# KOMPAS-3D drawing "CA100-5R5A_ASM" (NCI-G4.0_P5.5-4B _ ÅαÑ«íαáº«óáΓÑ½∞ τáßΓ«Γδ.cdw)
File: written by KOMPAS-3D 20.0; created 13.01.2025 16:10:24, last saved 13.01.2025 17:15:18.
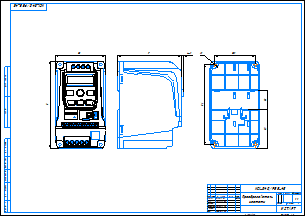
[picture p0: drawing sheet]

Sheet 1: A2, landscape

Document properties: Автор: admin; Полное имя файла: P:\INSTART\Технический отдел\ОР\Прочие задачи\КД на номенклатурный ряд\КД на типоразмеры ПЧ\NCI\NCI-G4.0_P5.5-4B\NCI-G4.0_P5.5-4B _ Преобразователь частоты.cdw

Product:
- Part/product: CA100-5R5A_ASM
    Масса: 7.13181
    Комментарий: NOT SPECIFIED
  - Component [detail]: AA  | Масса: 1.44663; source file: C:\Уралов Работа\Уралов (локальная)\ПЧ\! Китай 3Д-модель NCI\NCI 4.0-7.5 4B\AA.m3d
  - Component [detail]: CA100-2R2A-SJ-04  | Масса: 0.00516082; source file: C:\Уралов Работа\Уралов (локальная)\ПЧ\! Китай 3Д-модель NCI\NCI 4.0-7.5 4B\CA100-2R2A-SJ-04.m3d
  - Component [assembly]: JIANPAN99_ASM_ASM  | Масса: 0.107178; Комментарий: NOT SPECIFIED; source file: C:\Уралов Работа\Уралов (локальная)\ПЧ\! Китай 3Д-модель NCI\NCI 4.0-7.5 4B\JIANPAN99_ASM_ASM.a3d
  - Component [assembly]: CA100-5R5A-SJ_ASM  | Масса: 1.6976; Комментарий: NOT SPECIFIED; source file: C:\Уралов Работа\Уралов (локальная)\ПЧ\! Китай 3Д-модель NCI\NCI 4.0-7.5 4B\CA100-5R5A-SJ_ASM.a3d
  - Component [assembly]: PCB_ASM  | Масса: 1.9346; source file: C:\Уралов Работа\Уралов (локальная)\ПЧ\! Китай 3Д-модель NCI\NCI 4.0-7.5 4B\PCB_ASM.a3d
  - Component [assembly]: QJ_ASM  | Масса: 0.208727; source file: C:\Уралов Работа\Уралов (локальная)\ПЧ\! Китай 3Д-модель NCI\NCI 4.0-7.5 4B\QJ_ASM.a3d
  - Component [detail]: CA100-4R0A-SR-01  | Масса: 0.923365; source file: C:\Уралов Работа\Уралов (локальная)\ПЧ\! Китай 3Д-модель NCI\NCI 4.0-7.5 4B\CA100-4R0A-SR-01.m3d
  - Component [detail]: CA100-5R5A-SR-01  | Масса: 0.808548; source file: C:\Уралов Работа\Уралов (локальная)\ПЧ\! Китай 3Д-модель NCI\NCI 4.0-7.5 4B\CA100-5R5A-SR-01.m3d

Title block, sheet 1: Наименование: Преобразователь / частоты; designation: NCI-G4.0/P5.5-4B; Количество листов документа: 1; organisation: INSTART; cell 10: Согласовано; Форматы листов документа: A2; Разработал: Уралов Д.А.; Проверил: Андреев Н.В.; Подписал: Смелков Ж.Е.; Утвердил: Ефремов И.Н.; Разработал, date: 13.01.25

Views: Вид 1, Проекционный вид 2
Referenced files in C:\Уралов Работа\Уралов (локальная)\ПЧ\! Китай 3Д-модель NCI\NCI 4.0-7.5 4B\: CA100-4R0A-SR-01.m3d, CA100-5R5A-SR-01.m3d, 6025.m3d, QJ_ASM.a3d, QDB.m3d, DRI.m3d, 6912184100XX_MASS.m3d, 6912184100XX_PIN.m3d, 6912184100XX_VIS.m3d, 691218410003.m3d, ASSEM1_ASM.a3d, EU5-03-952_ASM.a3d, QDB_ASM.a3d, 2R2-CM.m3d, EU1_5-14-5_08-00_1_.m3d, LED.m3d, DWQ_2.m3d, ANJIAN.m3d, BM.m3d, 485.m3d, 2R2-CM_ASM.a3d, DRB.m3d, DR.m3d, DRB_ASM.a3d, PCB_ASM.a3d, CA100-5R5A-SJ-01.m3d, CA100-5R5A-SJ-02.m3d, CA100-5R5A-SJ-01-.m3d, CA100-5R5A-SJ_ASM.a3d, CA100-2R2A-SJ-05_45.m3d, CA100-2R2A-SJ-06_23.m3d, CA100-2R2A-SJ-03_22.m3d, JIANPAN99_ASM_17_ASM.a3d, JIANPAN99_ASM_ASM.a3d, CA100-2R2A-SJ-04.m3d, AA.m3d, NCI 4.0-7.5 4B.a3d
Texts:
  CA100-4R0A-SR-01
  CA100-4R0A-SR-01 CA100-4R0A-SR-01
  CA100-5R5A-SR-01
  CA100-5R5A-SR-01 CA100-5R5A-SR-01
  QJ_ASM QJ_ASM
  QDB
  QDB QDB
  DRI
  DRI DRI
  6912184100XX_MASS 6912184100XX_MASS
  6912184100XX_PIN 6912184100XX_PIN
  6912184100XX_VIS 6912184100XX_VIS
  ASSEM1_ASM ASSEM1_ASM
  EU5-03-952_ASM
  EU5-03-952_ASM EU5-03-952_ASM
  QDB_ASM QDB_ASM
  EU1_5-14-5_08-00_1_
  EU1_5-14-5_08-00_1_ EU1_5-14-5_08-00_1_
  LED
  LED LED
  DWQ_2 DWQ_2
  ANJIAN
  ANJIAN ANJIAN
  BM BM
  DRB
  DRB DRB
  DR DR
  DRB_ASM DRB_ASM
  PCB_ASM PCB_ASM
  CA100-5R5A-SJ-01
  CA100-5R5A-SJ-01 CA100-5R5A-SJ-01
  CA100-5R5A-SJ-02
  CA100-5R5A-SJ-02 CA100-5R5A-SJ-02
  CA100-5R5A-SJ-01-
  CA100-5R5A-SJ-01- CA100-5R5A-SJ-01-
  CA100-5R5A-SJ_ASM
  CA100-5R5A-SJ_ASM CA100-5R5A-SJ_ASM
  CA100-2R2A-SJ-05_45
  CA100-2R2A-SJ-05_45 CA100-2R2A-SJ-05_45
  CA100-2R2A-SJ-06_23
  CA100-2R2A-SJ-06_23 CA100-2R2A-SJ-06_23
  CA100-2R2A-SJ-03_22
  CA100-2R2A-SJ-03_22 CA100-2R2A-SJ-03_22
  JIANPAN99_ASM_17_ASM JIANPAN99_ASM_17_ASM
  JIANPAN99_ASM_ASM JIANPAN99_ASM_ASM
  Поверхности
  CA100-2R2A-SJ-04
  CA100-2R2A-SJ-04 CA100-2R2A-SJ-04
  AA AA
  CA100-5R5A_ASM
  CA100-5R5A_ASM CA100-5R5A_ASM
Dimensions and other numbers on the sheet: 4±1; 1:1; 1; 13.01.25; 6025; 6025 6025; 2R2-CM; 2R2-CM 2R2-CM; 485; 485 485; 2R2-CM_ASM; 2R2-CM_ASM 2R2-CM_ASM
